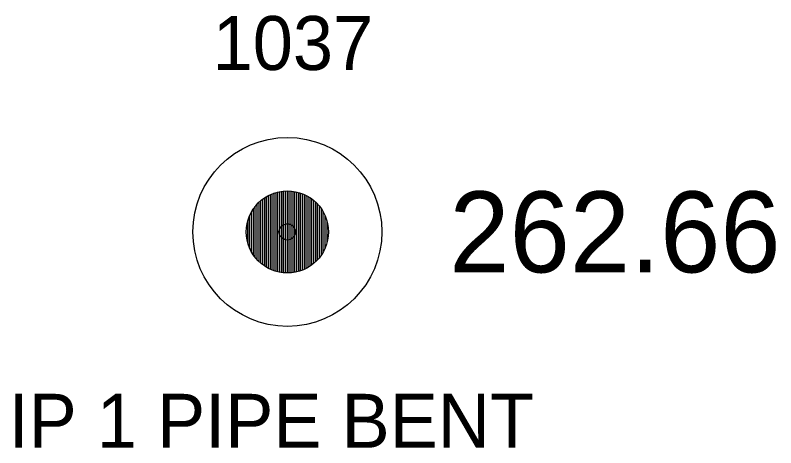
# Model space of a CAD drawing. Extents: x 1961231 to 1962574, y 799865 to 801120.
# Drawn here: x 1961857.64 to 1961871.73, y 800889.48 to 800897.49 of the extents above; entities that cross this region are included whole.
import ezdxf

# ---------------------------------------------------------------- set-up
doc = ezdxf.new("R2010")
doc.units = 0
for name, color, linetype in [('RD_EX_DV_Prop_txCode', 7, 'Continuous'), ('RD_EX_DV_PropPin', 7, 'Continuous'), ('RD_EX_TX_DV_Prop_ELEV', 7, 'Continuous'), ('RD_SMD_Locator', 7, 'Continuous')]:
    doc.layers.add(name, color=color, linetype=linetype)

msp = doc.modelspace()

# ---------------------------------------------------------------- linework, layer by layer
at = {"layer": 'RD_EX_DV_PropPin'}
for p, q in [((1961862.435, 800892.757), (1961862.435, 800894.198)), ((1961862.47, 800892.746), (1961862.47, 800894.209)), ((1961862.505, 800892.737), (1961862.505, 800894.218)), ((1961862.54, 800892.729), (1961862.54, 800894.225)), ((1961862.575, 800892.723), (1961862.575, 800894.231)), ((1961862.61, 800892.719), (1961862.61, 800894.235)), ((1961862.645, 800892.717), (1961862.645, 800894.237)), ((1961862.68, 800892.716), (1961862.68, 800894.238)), ((1961862.715, 800892.717), (1961862.715, 800894.237)), ((1961862.751, 800892.719), (1961862.751, 800894.235)), ((1961862.786, 800892.723), (1961862.786, 800894.231)), ((1961862.821, 800892.729), (1961862.821, 800894.225)), ((1961862.856, 800892.737), (1961862.856, 800894.218)), ((1961862.891, 800892.746), (1961862.891, 800894.209)), ((1961862.926, 800892.757), (1961862.926, 800894.198)), ((1961862.19, 800892.895), (1961862.19, 800894.059)), ((1961862.225, 800892.867), (1961862.225, 800894.087)), ((1961862.26, 800892.843), (1961862.26, 800894.112)), ((1961862.295, 800892.821), (1961862.295, 800894.134)), ((1961862.33, 800892.802), (1961862.33, 800894.153)), ((1961862.365, 800892.784), (1961862.365, 800894.17)), ((1961862.4, 800892.77), (1961862.4, 800894.185)), ((1961862.961, 800892.77), (1961862.961, 800894.185)), ((1961862.996, 800892.784), (1961862.996, 800894.17)), ((1961863.031, 800892.802), (1961863.031, 800894.153)), ((1961863.066, 800892.821), (1961863.066, 800894.134)), ((1961863.101, 800892.843), (1961863.101, 800894.112)), ((1961863.136, 800892.867), (1961863.136, 800894.087)), ((1961863.171, 800892.895), (1961863.171, 800894.059)), ((1961862.085, 800893.003), (1961862.085, 800893.951)), ((1961862.12, 800892.962), (1961862.12, 800893.992)), ((1961862.155, 800892.926), (1961862.155, 800894.028)), ((1961863.206, 800892.926), (1961863.206, 800894.028)), ((1961863.241, 800892.962), (1961863.241, 800893.992)), ((1961863.276, 800893.003), (1961863.276, 800893.951)), ((1961861.98, 800893.179), (1961861.98, 800893.775)), ((1961862.015, 800893.108), (1961862.015, 800893.847)), ((1961862.05, 800893.051), (1961862.05, 800893.904)), ((1961863.311, 800893.051), (1961863.311, 800893.904)), ((1961863.346, 800893.108), (1961863.346, 800893.847)), ((1961863.381, 800893.179), (1961863.381, 800893.775)), ((1961861.945, 800893.281), (1961861.945, 800893.673)), ((1961863.416, 800893.281), (1961863.416, 800893.673))]:
    msp.add_line(p, q, dxfattribs=at)
for radius in [1.75, 0.761]:
    msp.add_circle((1961862.68, 800893.477), radius, dxfattribs=at)
at = {"layer": 'RD_SMD_Locator'}
msp.add_circle((1961862.681, 800893.477), 0.15, dxfattribs=at)

# ---------------------------------------------------------------- texts
at = {"layer": 'RD_EX_DV_Prop_txCode'}
for s, p in [('1037', (1961861.295, 800896.477)), ('IP 1 PIPE BENT', (1961857.515, 800889.477))]:
    msp.add_text(s, height=1, dxfattribs=at).set_placement(p)
at = {"layer": 'RD_EX_TX_DV_Prop_ELEV'}
msp.add_text('262.66', height=1.5, dxfattribs=at).set_placement((1961865.681, 800892.727))

doc.saveas('drawing.dxf')
